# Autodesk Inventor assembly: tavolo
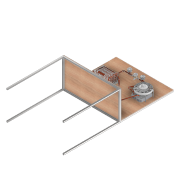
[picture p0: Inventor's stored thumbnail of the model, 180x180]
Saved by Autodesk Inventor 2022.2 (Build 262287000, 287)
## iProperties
_SolveAssemblyDoc: Frame Generator Solve Assembly
_Version: 25.0.0
Created: 2025-02
Part Number: tavolo
Document SubType Name: Assembly
Designer: 18907419
Author: 18907419
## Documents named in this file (13)
- C:\Users\18907419\Desktop\frigo_base\tavolo.iam
- C:\Users\18907419\Desktop\frigo_base\telaio_3D.ipt
- C:\Users\18907419\Desktop\frigo_base\Frame 1740559699060.iam
- C:\Users\18907419\Desktop\frigo_base\piano_v.ipt
- C:\Users\18907419\Desktop\frigo_base\160620 compressor.ipt
- C:\Users\18907419\Desktop\frigo_base\Alphacool NexXxoS XT45 180mm Single.iam
- C:\Users\18907419\Desktop\frigo_base\001.001.00009.ipt
- C:\Users\18907419\Desktop\frigo_base\DML 052.ipt
- C:\Users\18907419\Desktop\frigo_base\BML12S - 1-2in.ipt
- C:\Users\18907419\Desktop\frigo_base\Manômetro 7 bar.ipt
- C:\Users\18907419\Desktop\frigo\tubi.ipt
- C:\Users\18907419\Desktop\frigo_base\evaporatore.step.ipt
- C:\Users\18907419\Desktop\frigo_base\raccordi_t.ipt
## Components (14 placed, 12 different names)
1. telaio_3D:1
2. Frame 1740559699060:1 [sub-assembly] — Allineato:1, Allineato:2, Allineato:3, Angolo:5, Angolo:6
3. piano_v:1 — Allineato:1, Allineato:2, Allineato:3, Coincidente:1, Coincidente:3, Coincidente:4, Coincidente:10, Coincidente:11, Coincidente:12
4. 160620 compressor:1 — Coincidente:1, Rotazionale:1, Allineato:8, Allineato:10
5. Alphacool NexXxoS XT45 180mm Single:1 [sub-assembly] — Coincidente:3, Allineato:11, Allineato:13
6. 001.001.00009:1 — Coincidente:4
7. DML 052:1 — Rotazionale:1, Allineato:7, Allineato:9
8. BML12S - 1-2in:1 — Coincidente:10, Allineato:12, Allineato:14
9. evaporatore.step:1 — Coincidente:11, Coincidente:12, Allineato:5, Allineato:6
10. tubi:1 — Allineato:5, Allineato:6, Allineato:7, Allineato:8, Allineato:9, Allineato:10, Allineato:11, Allineato:12, Allineato:13, Allineato:14, Coincidente:15, Coincidente:16
11. raccordi_t:1 — Coincidente:15, Angolo:5, Rigido:1
12. Manômetro 7 bar:2
13. raccordi_t:2 — Coincidente:16, Angolo:6, Rigido:2
14. Manômetro 7 bar:3
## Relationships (26: Flush 13, Mate 8, Angle 2, WeldJoint 2, RevoluteJoint 1)
- Allineato:1 [Flush]: Frame 1740559699060:1 ↔ piano_v:1
- Allineato:2 [Flush]: Frame 1740559699060:1 ↔ piano_v:1
- Allineato:3 [Flush]: Frame 1740559699060:1 ↔ piano_v:1
- Coincidente:1 [Mate]: piano_v:1 ↔ 160620 compressor:1
- Coincidente:3 [Mate]: piano_v:1 ↔ Alphacool NexXxoS XT45 180mm Single:1
- Coincidente:4 [Mate]: piano_v:1 ↔ 001.001.00009:1
- Rotazionale:1 [RevoluteJoint]: 160620 compressor:1 ↔ DML 052:1
- Coincidente:10 [Mate]: piano_v:1 ↔ BML12S - 1-2in:1
- Coincidente:11 [Mate]: piano_v:1 ↔ evaporatore.step:1
- Coincidente:12 [Mate]: piano_v:1 ↔ evaporatore.step:1
- Allineato:5 [Flush]: evaporatore.step:1 ↔ tubi:1
- Allineato:6 [Flush]: evaporatore.step:1 ↔ tubi:1
- Allineato:7 [Flush]: DML 052:1 ↔ tubi:1
- Allineato:8 [Flush]: 160620 compressor:1 ↔ tubi:1
- Allineato:9 [Flush]: DML 052:1 ↔ tubi:1
- Allineato:10 [Flush]: 160620 compressor:1 ↔ tubi:1
- Allineato:11 [Flush]: Alphacool NexXxoS XT45 180mm Single:1 ↔ tubi:1
- Allineato:12 [Flush]: BML12S - 1-2in:1 ↔ tubi:1
- Allineato:13 [Flush]: Alphacool NexXxoS XT45 180mm Single:1 ↔ tubi:1
- Allineato:14 [Flush]: BML12S - 1-2in:1 ↔ tubi:1
- Coincidente:15 [Mate]: tubi:1 ↔ raccordi_t:1
- Angolo:5 [Angle]: Frame 1740559699060:1 ↔ raccordi_t:1
- Rigido:1 [WeldJoint]: raccordi_t:1
- Coincidente:16 [Mate]: tubi:1 ↔ raccordi_t:2
- Angolo:6 [Angle]: Frame 1740559699060:1 ↔ raccordi_t:2
- Rigido:2 [WeldJoint]: raccordi_t:2
